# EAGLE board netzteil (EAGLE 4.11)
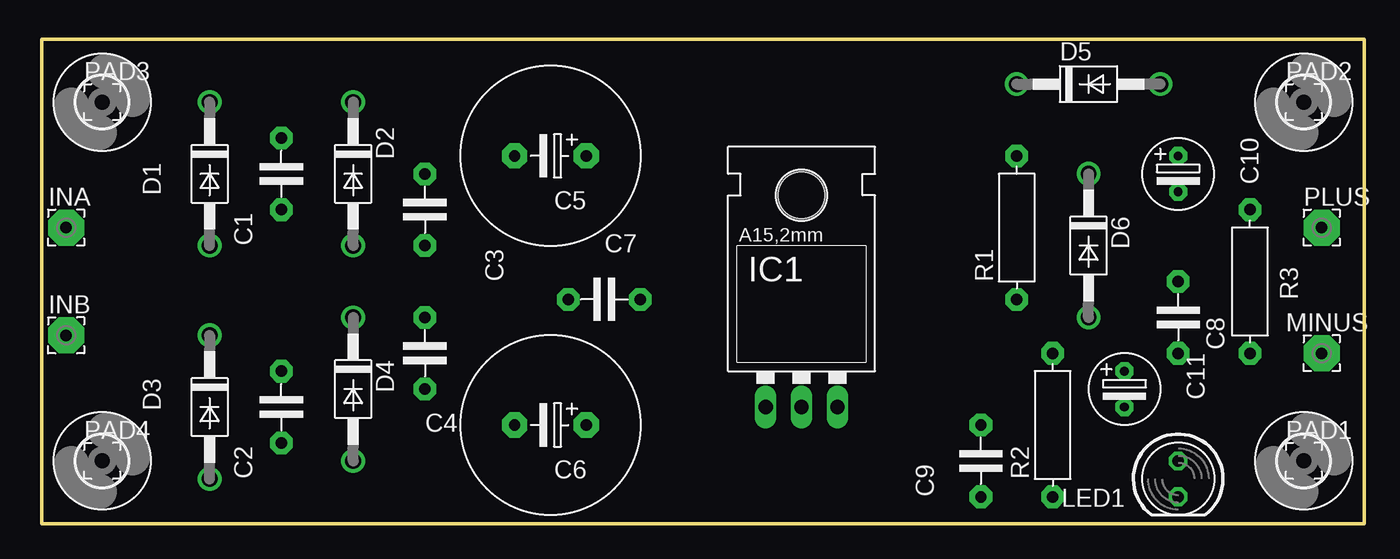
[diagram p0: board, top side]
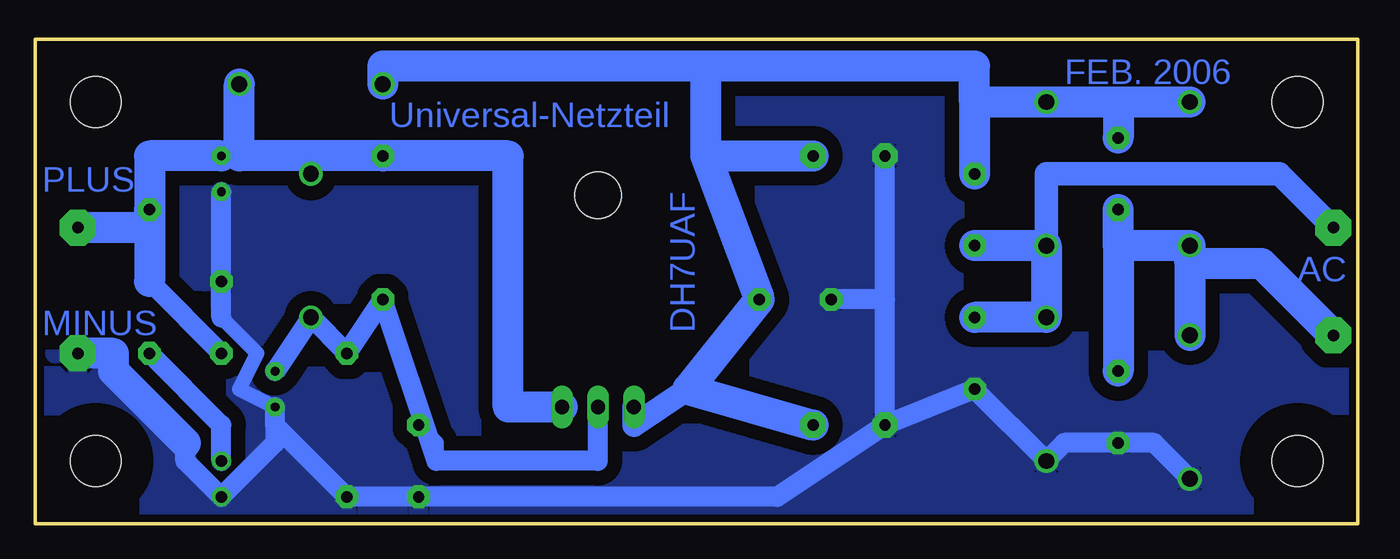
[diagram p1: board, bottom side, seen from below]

Size 93.65 x 34.28 mm. Coordinates in mm from the lower left corner, seen from the top.
Outline: 0,0 93.65,0 93.65,34.28 0,34.28 0,0
Copper layers (1*16): Top 0.035mm / dielectric 1.5mm / Bottom 0.035mm
Design rules "default": minimum track width 10mil, minimum drill 24mil, track to track 40mil, track to pad 40mil, pad to pad 20mil, via to via 8mil, smd to smd 8mil, copper to edge 20mil, drill to drill 8mil, minimum pad ring 10mil, minimum via ring 8mil, stop-mask expansion 4mil, vias tented up to drill 0mil, thermal gap 10mil

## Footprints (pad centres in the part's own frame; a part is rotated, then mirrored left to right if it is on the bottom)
C-5 = drill 0.813 pad 1.6 octagon: 1 -2.54,0; 2 2.54,0
ES-5L = drill 0.813 pad 1.778 octagon: 1 0,0; 2 5.08,0
ES-2,5L = drill 0.61 pad 1.27 octagon: 1 0,0; 2 2.54,0
DO41-10 = drill 1.118 round: A 5.08,0; C -5.08,0
3,6 = hole 3.6: 0,0
78XXL = drill 1.016 long: GND 0,-3.81; IN -2.54,-3.81; OUT 2.54,-3.81 | hole 3.302: 0,11.176
2,54/0,8 = drill 0.813 pad 2.54 octagon: 1 0,0
LED5MM = drill 0.813 octagon: A -1.27,0; K 1.27,0
R-10 = drill 0.813 pad 1.6 octagon: 1 -5.08,0; 2 5.08,0

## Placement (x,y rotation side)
C1  100 nF  [C-5]  16.98,24.76 90 top
C2  100 nF  [C-5]  16.98,8.25 90 top
C3  100 nF  [C-5]  27.14,22.22 90 top
C4  100 nF  [C-5]  27.14,12.06 90 top
C5  [ES-5L]  38.57,26.03 180 top
C6  [ES-5L]  38.57,6.98 180 top
C7  100 nF  [C-5]  39.84,15.87 0 top
C8  100 nF  [C-5]  80.48,14.6 270 top
C9  100 nF  [C-5]  66.51,4.44 90 top
C10  10 µF  [ES-2,5L]  80.48,26.03 270 top
C11  10 µF  [ES-2,5L]  76.67,10.79 270 top
D1  1N4004  [DO41-10]  11.9,24.76 270 top
D2  1N4004  [DO41-10]  22.06,24.76 270 top
D3  1N4004  [DO41-10]  11.9,8.25 270 top
D4  1N4004  [DO41-10]  22.06,9.52 270 top
D5  1N4004  [DO41-10]  74.13,31.11 0 top
D6  1N4004  [DO41-10]  74.13,19.68 270 top
H1  MOUNT-HOLE3.6  [3,6]  4.28,29.84 0 top
H2  MOUNT-HOLE3.6  [3,6]  4.28,4.44 0 top
H3  MOUNT-HOLE3.6  [3,6]  89.37,29.84 0 top
H4  MOUNT-HOLE3.6  [3,6]  89.37,4.44 0 top
IC1  [78XXL]  53.81,12.06 0 top
INA  [2,54/0,8]  1.74,20.95 0 top
INB  [2,54/0,8]  1.74,13.33 0 top
LED1  [LED5MM]  80.48,3.17 270 top
MINUS  [2,54/0,8]  90.64,12.06 0 top
PAD1  [2,54/0,8]  89.37,4.44 0 top
PAD2  [2,54/0,8]  89.37,29.84 0 top
PAD3  [2,54/0,8]  4.28,29.84 0 top
PAD4  [2,54/0,8]  4.28,4.44 0 top
PLUS  [2,54/0,8]  90.64,20.95 0 top
R1  [R-10]  69.05,20.95 90 top
R2  [R-10]  71.59,6.98 90 top
R3  [R-10]  85.56,17.14 90 top

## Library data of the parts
C1-C11 R1-R3 = discrete
D1-D6 = diode
H1-H4 = holes
IC1 = v-reg
INA INB MINUS PAD1-PAD4 PLUS = wirepad
LED1 = led

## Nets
GND: C2.1 C4.1 C5.2 C6.2 C7.1 C8.1 C9.1 C10.2 C11.2 D3.A D4.A LED1.K MINUS.1 R2.1
N$1: C1.2 C3.2 C5.1 C6.1 C7.2 D1.C D2.C D5.C IC1.IN
N$2: C8.2 C10.1 D5.A D6.C IC1.OUT PLUS.1 R1.2 R3.2
N$3: C9.2 C11.1 D6.A IC1.GND R1.1 R2.2
N$8: LED1.A R3.1
N$16: C1.1 C2.2 D1.A D3.C INB.1
S$2: C3.1 C4.2 D2.A D4.C INA.1

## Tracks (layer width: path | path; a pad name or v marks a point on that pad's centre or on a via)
GND
  Bottom 1.016: 80.48,14.6 77.94,12.06 79.21,9.52 C11.2
  Bottom 1.422: C10.2 C8.1 80.48,14.6 | 76.67,6.98 C11.2 | 83.02,5.71 83.02,4.44 LED1.K 76.67,5.71 76.67,6.98 | D3.A 14.44,5.71 C2.1 20.79,5.71 D4.A C4.1 C6.2 | 33.49,15.87 C7.1 | 33.49,15.87 C5.2 | C6.2 33.49,15.87 | 76.67,6.98 R2.1 C9.1 41.11,1.9 C6.2
  Bottom 2.184: MINUS.1 88.1,12.06 88.1,10.79 83.02,5.71
  pour Bottom: -2.07,37.46 -2.07,-1.91 96.99,-1.91 96.99,37.46
N$1
  Bottom 0.254: D2.C 16.98,29.84
  Bottom 1.676: IC1.IN 51.27,6.98 47.46,9.52
  Bottom 2.184: C6.1 47.46,9.52 C7.2 46.19,26.03 | 46.19,26.03 C5.1 | D5.C 69.05,32.38 46.19,32.38 | 46.19,32.38 46.19,26.03 | 46.19,32.38 27.14,32.38 27.14,29.84 | 27.14,29.84 C3.2 | 16.98,29.84 C1.2 | 27.14,29.84 D2.C D1.C
N$2
  Bottom 0.254: IC1.OUT 56.35,9.52
  Bottom 1.422: 85.56,17.14 C8.2 | 79.21,26.03 C10.1 | 74.13,26.03 D6.C
  Bottom 2.184: 85.56,20.95 R3.2 85.56,26.03 C10.1 | 85.56,20.95 85.56,17.14 | 85.56,20.95 PLUS.1 | D5.A 79.21,26.03 74.13,26.03 R1.2 60.16,26.03 60.16,8.25 IC1.OUT
N$3
  Bottom 1.016: 65.24,4.44 65.24,5.71 C9.2
  Bottom 1.422: C11.1 D6.A R2.2 R1.1 65.24,4.44 53.81,4.44 IC1.GND
N$8
  Bottom 1.422: LED1.A 80.48,6.98 R3.1
N$16
  Bottom 2.184: 16.98,19.68 C2.2 | 16.98,19.68 C1.1 | 16.98,19.68 D1.A 11.9,18.41 | 11.9,18.41 D3.C | INB.1 6.82,18.41 11.9,18.41
S$2
  Bottom 1.676: D2.A 22.06,24.76 5.55,24.76 INA.1
  Bottom 2.184: C4.2 D4.C D2.A C3.1

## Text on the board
Bottom: FEB. 2006 | Universal-Netzteil | DH7UAF | PLUS | AC | MINUS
